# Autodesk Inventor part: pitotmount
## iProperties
Created: 2010-03
Part Number: pitotmount
Document SubType Name: Modeling
Designer: a31883
Density: 1 g/cm^3
Author: a31883
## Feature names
1. Extrusion1
2. Extrusion2
3. Extrusion3
4. Mirror1
5. Extrusion4
6. Extrusion5
7. Extrusion6
